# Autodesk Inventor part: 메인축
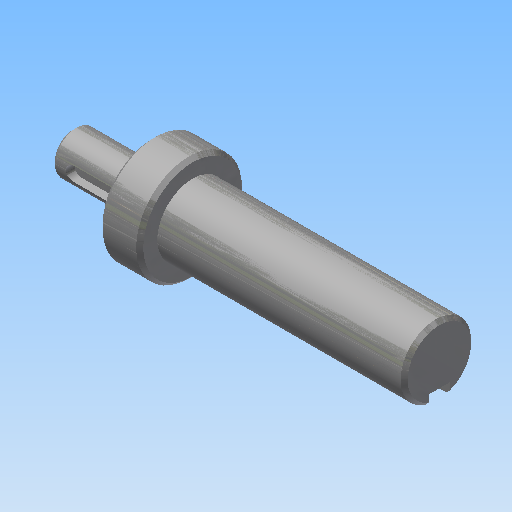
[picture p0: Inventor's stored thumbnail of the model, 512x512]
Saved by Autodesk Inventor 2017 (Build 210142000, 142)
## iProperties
Created: 2018-09
Part Number: 메인축
Document SubType Name: Modeling
Density: 1 g/cm^3
Material: 강철, 연강
Appearance: 강철
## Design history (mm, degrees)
sketch "스케치1"
  geometry: L1 (34.997, -37.5)-(34.997, -77.5) reference; L2 (46.5, -38.401)-(46.5, -76.599) reference; L3 (12.497, -57.5)-(116.5, -57.5); L4 (12.497, -63.5)-(34.997, -63.5); L5 (34.997, -72.5)-(46.5, -72.5); L6 (46.5, -67.5)-(116.5, -67.5); L7 (116.5, -67.5)-(116.5, -57.5); L8 (12.497, -63.5)-(12.497, -57.5); 2 further points
  constraints: 12 end point, 5 point on line, 4 perpendicular, 1 midpoint, 1 parallel
  dimensions: "d0" = 20 diameter of L6 L3; "d1" = 30 diameter of L5 L3; "d2" = 22.5 distance of L4.start L4.end; "d3" = 70 distance of L6.start L6.end; "d5" = 12 diameter of L4 L3
revolve "회전1" sketch "스케치1" stored, may be unused: angle "d4" = 90 deg
chamfer "모따기1" distance "d6" = 1; stored, may be unused: second distance "d7" = 2, angle "d8" = 45 deg
node "작업 평면1"
sketch "스케치2"
  geometry: L1 (-11.25, -5)-(-11.25, 5) reference; L2 (-5.25, 2)-(4.75, 2); L3 (4.75, -2)-(-5.25, -2); A1 r 2 centre (4.75, 0) between (4.75, -2) and (4.75, 2); A2 r 2 centre (-5.25, 0) between (-5.25, 2) and (-5.25, -2); 2 further points
  constraints: 4 end point, 4 point on circle, 4 tangent, 2 centre point, 1 horizontal alignment, 1 midpoint, 1 parallel, 1 perpendicular
  dimensions: "d9" = 4 distance between parallel lines of L3 L2; "d10" = 14 dimension on A1 A2; "d11" = 4 distance edge to line of A2 L1
extrude "돌출1" cut sketch "스케치2" distance "d12" = 2.5; taper "d13" = 0 deg
node "작업 평면2"
sketch "스케치3"
  geometry: L1 (35, 9)-(35, -9) reference; L2 (35, 3)-(20, 3); L3 (20, -3)-(35, -3); A1 r 3 centre (20, 0) between (20, 3) and (20, -3); 2 further points
  constraints: 4 end point, 2 perpendicular, 2 point on circle, 2 point on line, 2 tangent, 1 centre point, 1 horizontal alignment, 1 midpoint
  dimensions: "d14" = 6 distance between parallel lines of L3 L2; "d15" = 18 dimension on A1 L1
extrude "돌출2" cut sketch "스케치3" distance "d16" = 3.5; taper "d17" = 0 deg
node "솔리드1"
node "참조1"
node "참조2"
